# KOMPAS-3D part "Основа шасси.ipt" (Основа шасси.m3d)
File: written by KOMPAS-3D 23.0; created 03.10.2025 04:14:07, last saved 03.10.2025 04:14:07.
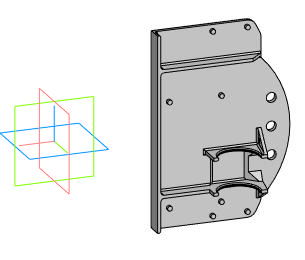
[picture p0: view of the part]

Document properties: Автор: Lost; Полное имя файла: C:\Users\Lost\Downloads\Telegram Desktop\ИМ-ИТ ЦД\ИМ-ИТ ЦД\Вариант 12\Основа шасси.ipt.m3d

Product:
- Part/product: Основа шасси.ipt

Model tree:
1. Операция без истории:1
2. Операция без истории:2
3. Операция без истории:3
4. Операция без истории:4
5. Операция без истории:5
6. Операция без истории:6
7. Операция без истории:7
8. Операция без истории:8
9. Операция без истории:9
